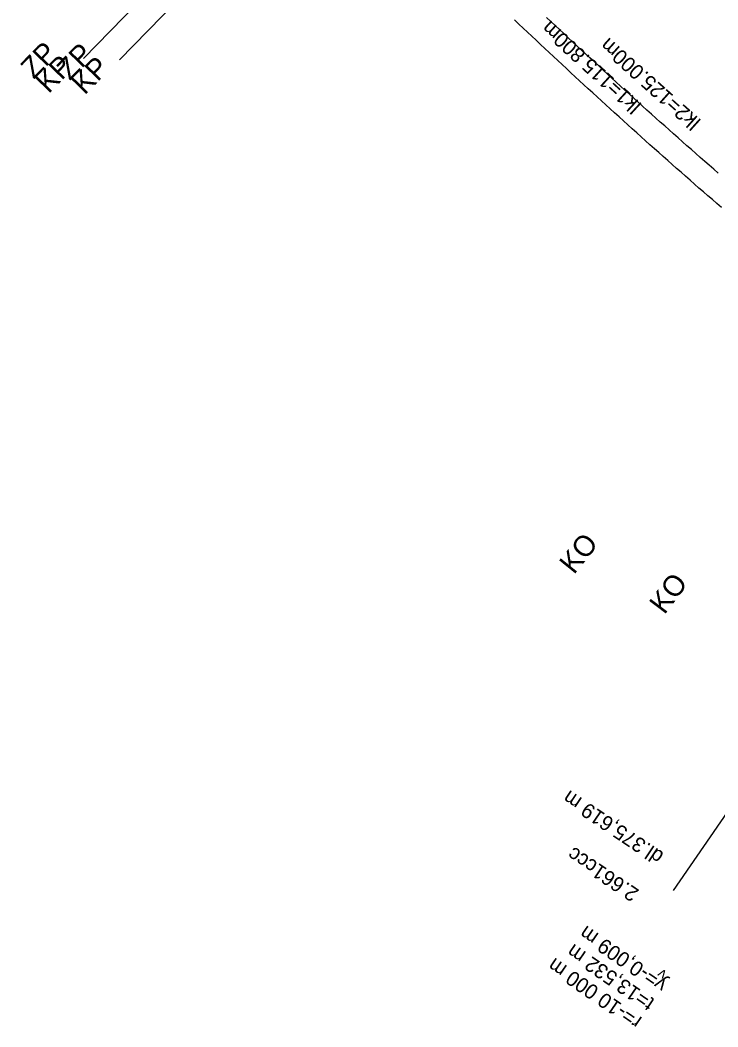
# Model space of a CAD drawing. Extents: x -825429 to 825387, y -1070027 to 1069917.
# Drawn here: x -824785.1 to -824667.7, y -1069948.1 to -1069778.7 of the extents above; entities that cross this region are included whole.
import ezdxf

# ---------------------------------------------------------------- set-up
doc = ezdxf.new("R2010")
doc.units = 0
doc.layers.add('NEW KOLEJE PALKOBAR', color=7, linetype='Continuous')
doc.layers.add('NEW KOLEJE VLADO PROVI', color=7, linetype='Continuous')

msp = doc.modelspace()

# ---------------------------------------------------------------- linework, layer by layer
at = {"layer": 'NEW KOLEJE PALKOBAR'}
for points in [[(-824667.07, -1069810.19), (-824667.82, -1069809.54), (-824668.58, -1069808.88), (-824669.34, -1069808.23), (-824670.09, -1069807.57), (-824670.85, -1069806.92), (-824671.6, -1069806.26), (-824672.35, -1069805.6), (-824673.1, -1069804.94), (-824673.85, -1069804.28), (-824674.6, -1069803.62), (-824675.35, -1069802.96), (-824676.1, -1069802.29), (-824676.85, -1069801.63), (-824677.6, -1069800.96), (-824678.34, -1069800.3), (-824679.09, -1069799.63), (-824679.83, -1069798.97), (-824680.58, -1069798.3), (-824681.32, -1069797.63), (-824682.06, -1069796.96), (-824682.81, -1069796.29), (-824683.55, -1069795.62), (-824684.29, -1069794.95), (-824685.03, -1069794.27), (-824685.77, -1069793.6), (-824686.51, -1069792.93), (-824687.25, -1069792.25), (-824687.98, -1069791.58), (-824688.72, -1069790.9), (-824689.46, -1069790.22), (-824690.19, -1069789.55), (-824690.93, -1069788.87), (-824691.66, -1069788.19), (-824692.4, -1069787.51), (-824693.13, -1069786.83), (-824693.86, -1069786.15), (-824694.59, -1069785.47), (-824695.33, -1069784.79), (-824696.06, -1069784.11), (-824696.79, -1069783.42), (-824697.52, -1069782.74), (-824698.25, -1069782.06), (-824698.98, -1069781.37), (-824699.71, -1069780.69), (-824700.43, -1069780), (-824701.16, -1069779.32), (-824701.89, -1069778.63)], [(-824667.61, -1069804.41), (-824668.36, -1069803.75), (-824669.12, -1069803.09), (-824669.87, -1069802.44), (-824670.62, -1069801.78), (-824671.37, -1069801.12), (-824672.12, -1069800.46), (-824672.87, -1069799.8), (-824673.62, -1069799.13), (-824674.37, -1069798.47), (-824675.12, -1069797.8), (-824675.87, -1069797.14), (-824676.61, -1069796.47), (-824677.36, -1069795.81), (-824678.1, -1069795.14), (-824678.84, -1069794.47), (-824679.59, -1069793.8), (-824680.33, -1069793.13), (-824681.07, -1069792.46), (-824681.81, -1069791.79), (-824682.55, -1069791.11), (-824683.29, -1069790.44), (-824684.03, -1069789.77), (-824684.77, -1069789.09), (-824685.5, -1069788.41), (-824686.24, -1069787.74), (-824686.98, -1069787.06), (-824687.71, -1069786.38), (-824688.44, -1069785.7), (-824689.18, -1069785.03), (-824689.91, -1069784.35), (-824690.64, -1069783.66), (-824691.38, -1069782.98), (-824692.11, -1069782.3), (-824692.84, -1069781.62), (-824693.57, -1069780.94), (-824694.3, -1069780.25), (-824695.03, -1069779.57), (-824695.76, -1069778.88), (-824696.49, -1069778.2)]]:
    msp.add_lwpolyline(points, dxfattribs=at)
at = {"layer": 'NEW KOLEJE VLADO PROVI'}
for points in [[(-824774.4, -1069785.13), (-824736.03, -1069745.73)], [(-824768.32, -1069785.36), (-824729.94, -1069745.97)], [(-824675.13, -1069925.15), (-824618.39, -1069842.81)]]:
    msp.add_lwpolyline(points, dxfattribs=at)

# ---------------------------------------------------------------- texts
for s, height, rotation, p in [('lk1=115.800m', 2.5, 137.5213, (-824680.34, -1069792.82)), ('ZP', 3.5, 45.762, (-824782.77, -1069788.71)), ('ZP', 3.5, 45.742, (-824776.7, -1069788.93)), ('lk2=125.000m', 2.5, 138.1054, (-824670.36, -1069795.55)), ('KP', 3.5, 45.762, (-824780.26, -1069791.15)), ('KP', 3.5, 45.742, (-824774.19, -1069791.37)), ('KO', 3.5, 51.0403, (-824691.88, -1069872.1)), ('KO', 3.5, 52.8331, (-824676.66, -1069878.85)), ('dl.375,619 m', 2.5, 146.2308, (-824676.59, -1069918.92)), ('2.661ccc', 2.5, 146.2308, (-824680.76, -1069925.16)), ('y=-0,009 m', 2.5, 145.4334, (-824675.99, -1069940.5)), ('t=13,532 m', 2.5, 145.4334, (-824678.11, -1069943.59)), ('r=-10 000 m', 2.5, 145.4334, (-824680.24, -1069946.67)), ('v', 1.8, 145.4334, (-824676.12, -1069938.93))]:
    msp.add_text(s, height=height, rotation=rotation, dxfattribs=at).set_placement(p)

doc.saveas('drawing.dxf')
